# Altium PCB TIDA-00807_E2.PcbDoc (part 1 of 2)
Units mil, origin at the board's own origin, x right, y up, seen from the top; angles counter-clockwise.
Board outline 2559.06 x 2559.06 mil, 2 copper layers (Top Layer, Bottom Layer), stack 62 mil thick; 165 components, 78 nets, 356 pads, 106 vias.
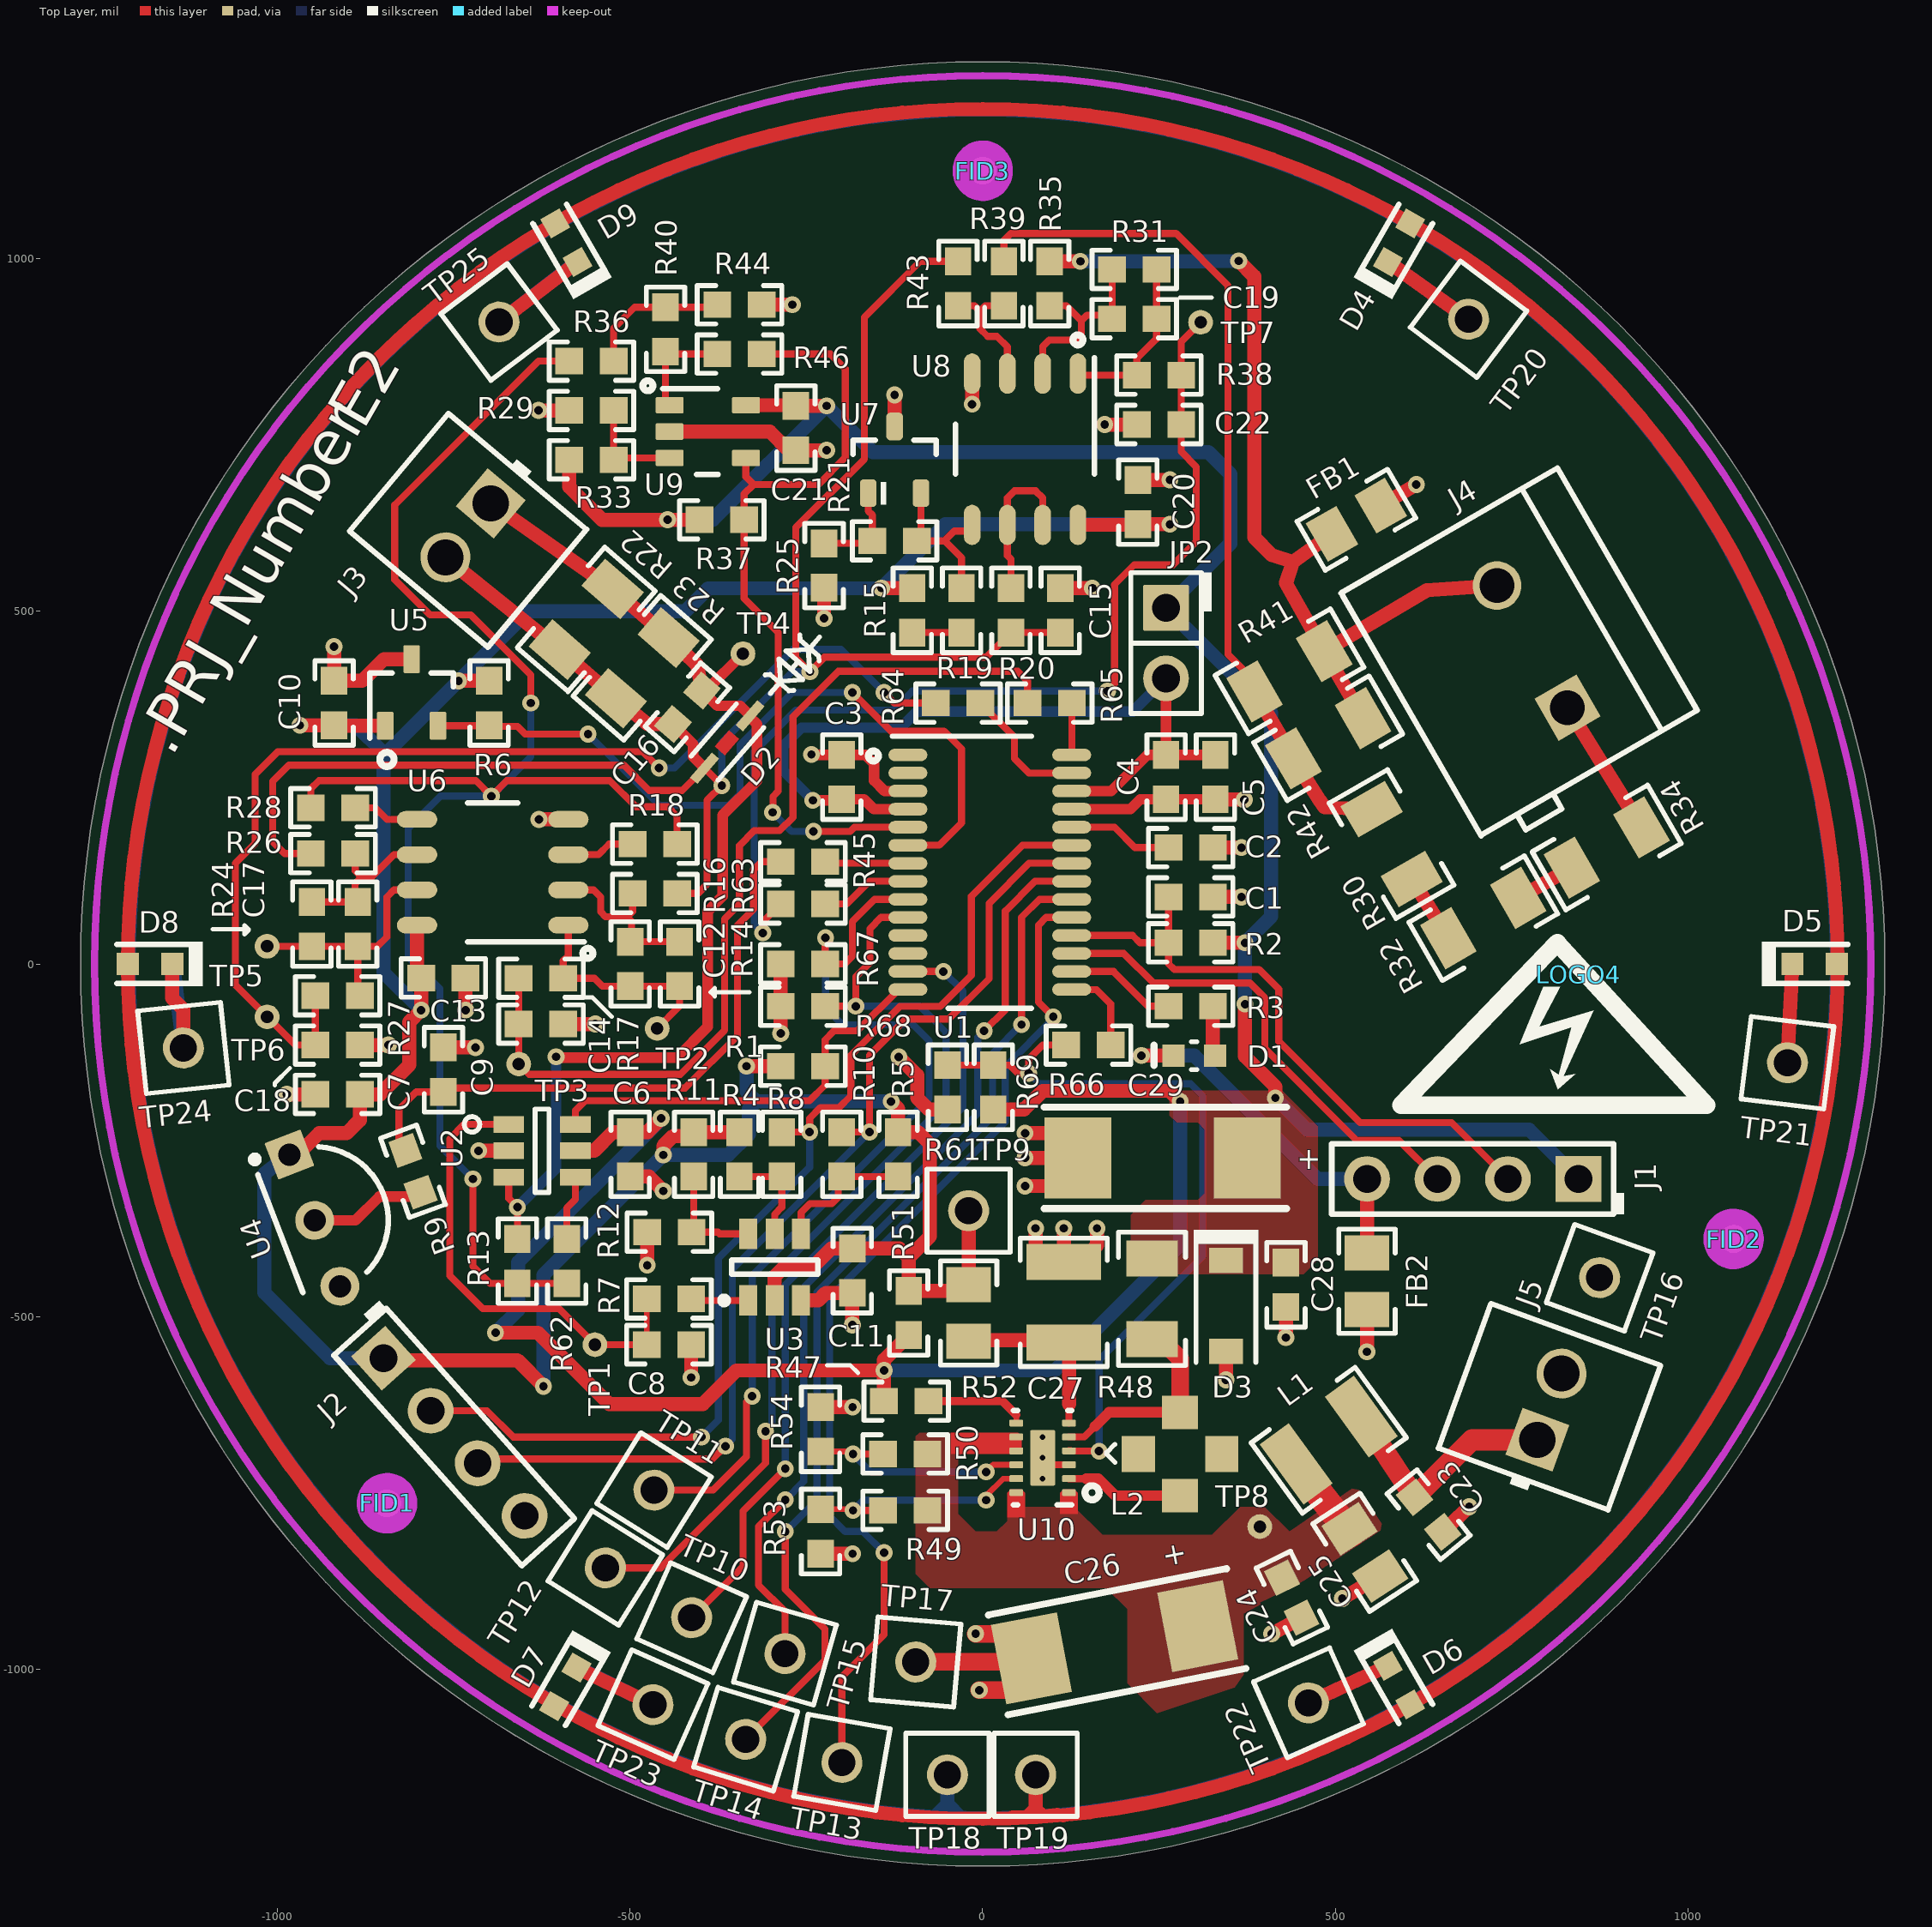
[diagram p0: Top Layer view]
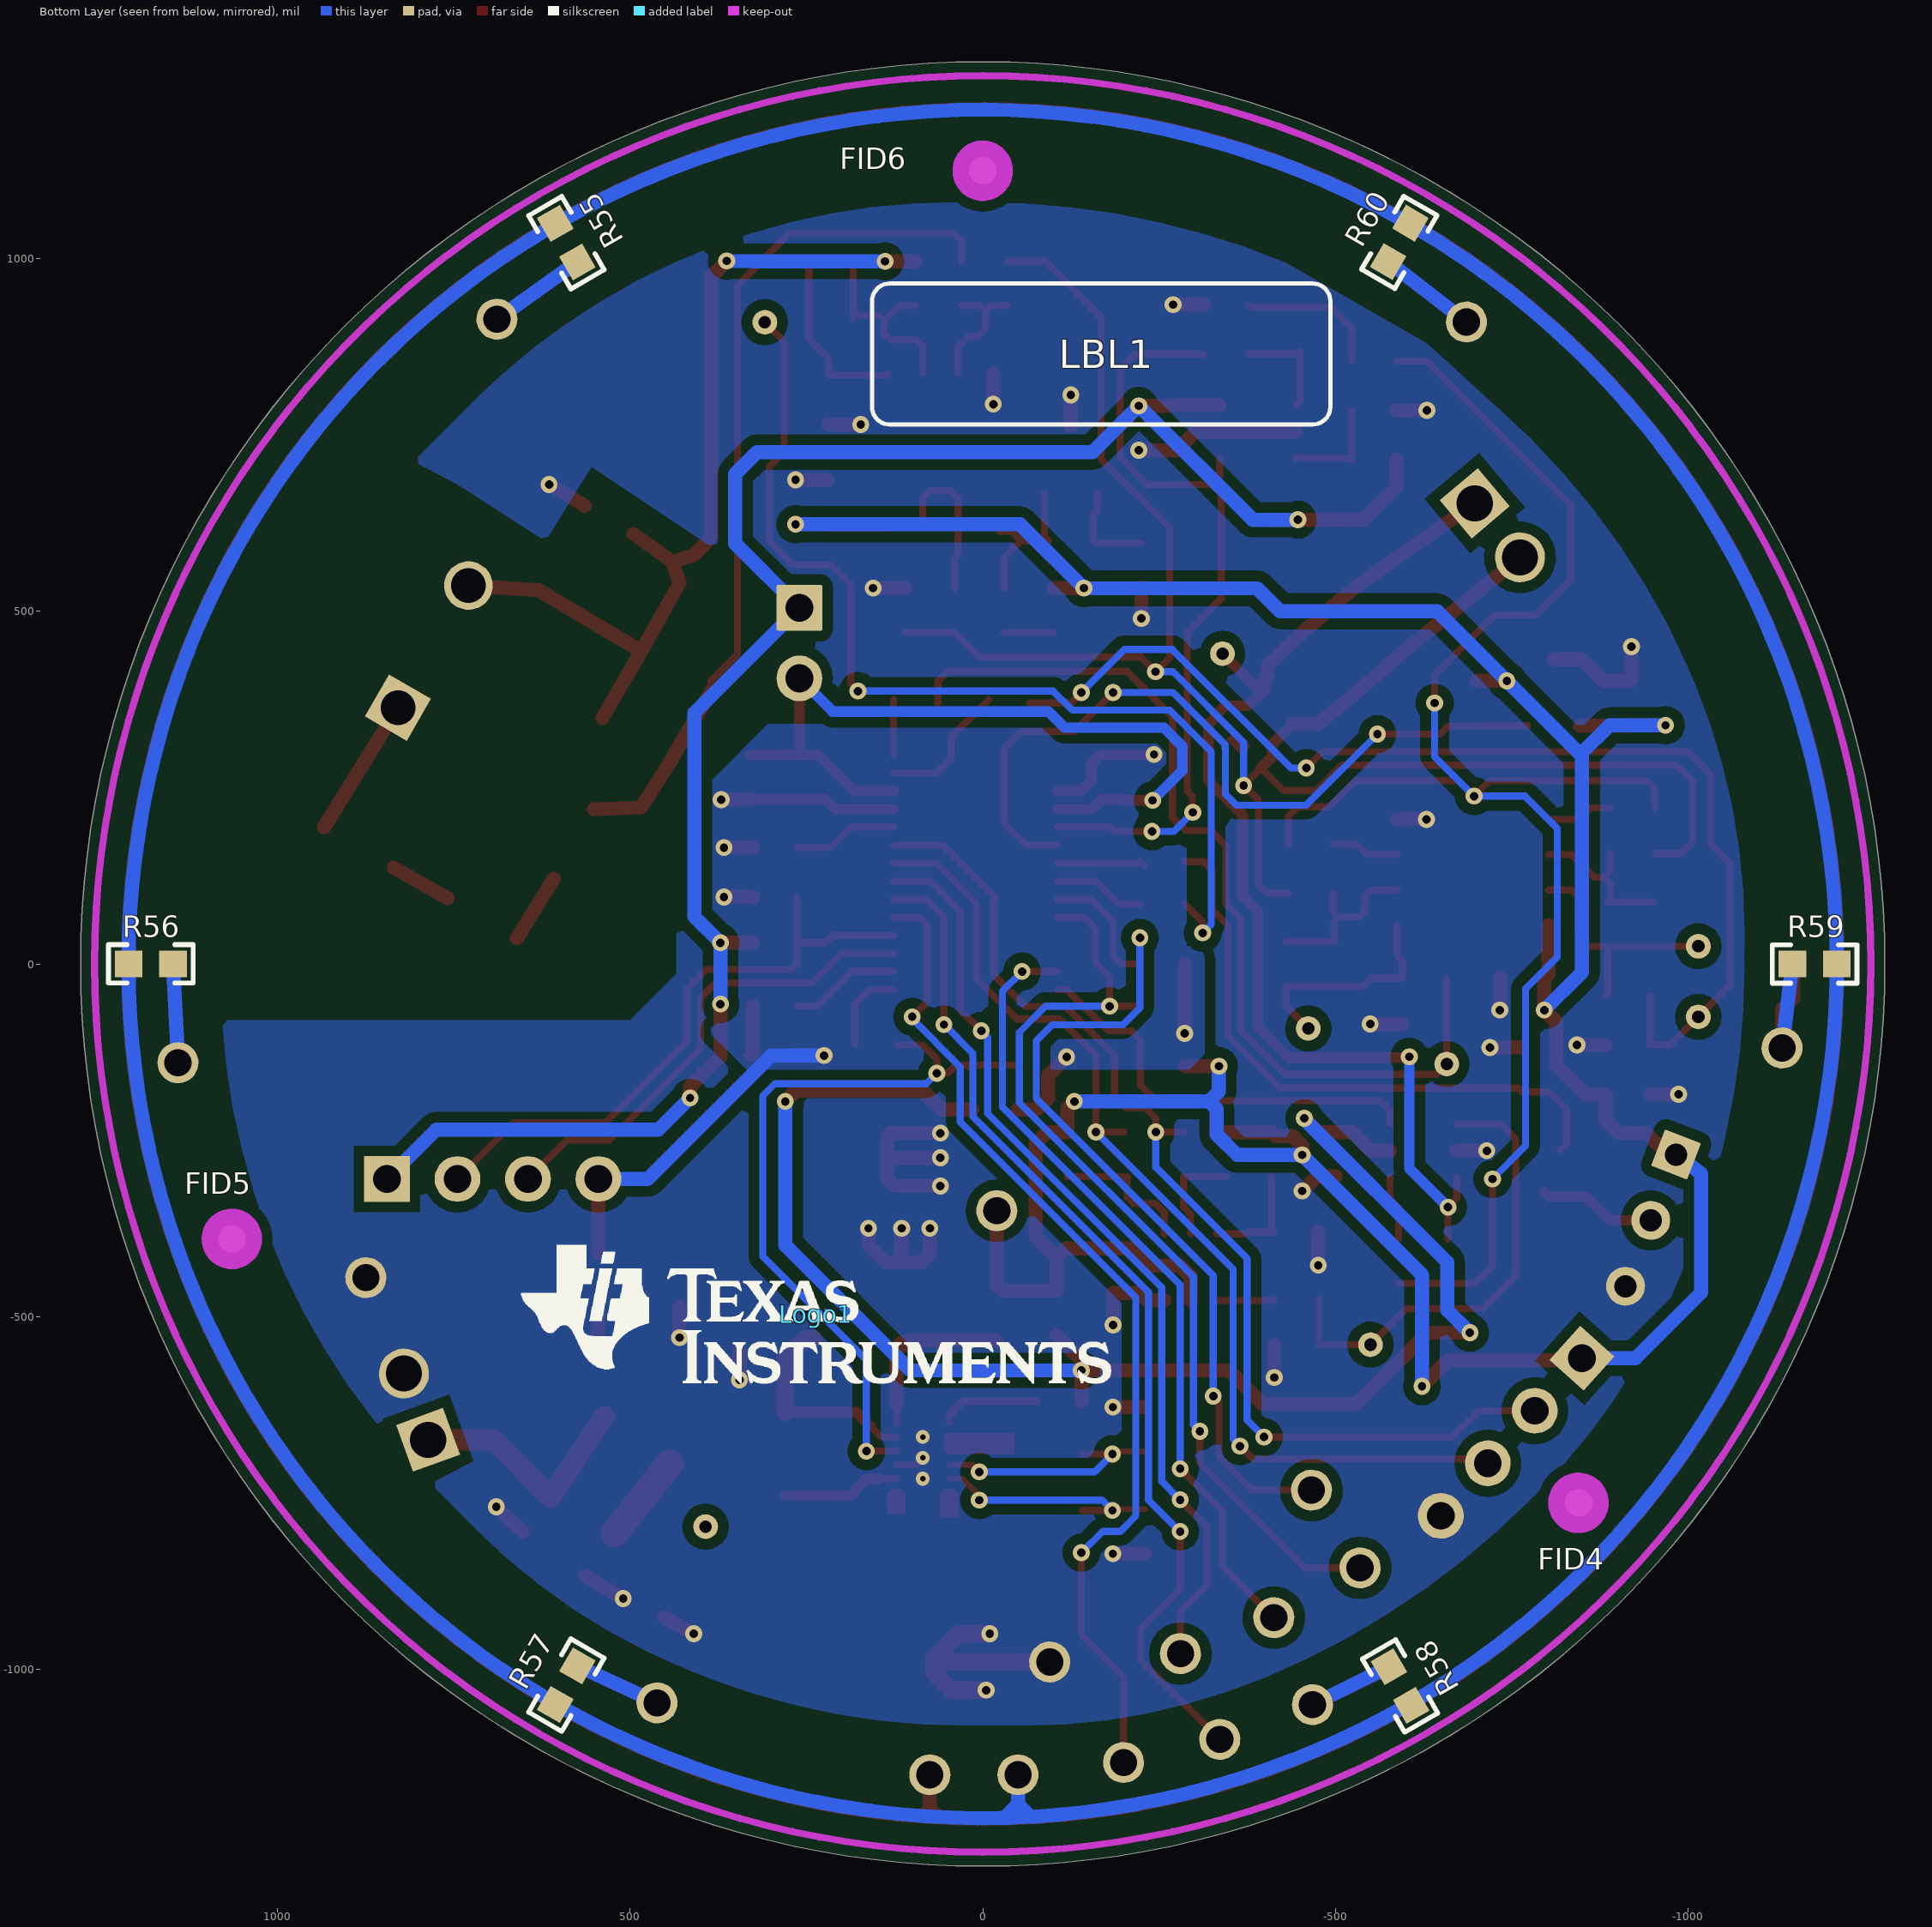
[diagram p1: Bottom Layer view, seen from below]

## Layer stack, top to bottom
Top Layer: signal copper 1.4
Dielectric: core 59.2, FR-4 High Tg, Dk 4.8
Bottom Layer: signal copper 1.4

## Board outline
0,-1279.53 cw(c0,0) -1279.53,0 cw(c0,0) 0,1279.53 cw(c0,0) 1279.53,0 cw(c0,0)

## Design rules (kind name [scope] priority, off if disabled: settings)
AcuteAngle [All] p1: minimum=4.50000000000000E+0001 checktracksonly=FALSE
AssemblyTestPointUsage [All] p1: valid=2
Clearance Clearance_Poly [InPolygon] p1: gap=15
Clearance [All] p2: gap=7.87
ComponentClearance ComponentClearance_MountingHoles_FiducialMarks [InComponentClass('Mounting Holes') vs InComponentClass('FiducialMark')] p1: gap=50 collisioncheckmode=3 verticalgap=10 showdistances=FALSE
ComponentClearance ComponentClearance_Shunt [InComponentClass('Header') vs InComponentClass('Shunt')] p2: gap=0 collisioncheckmode=3 verticalgap=0 showdistances=FALSE
ComponentClearance ComponentClearance_Logo [InComponentClass('Logo')] p3: gap=50 collisioncheckmode=3 verticalgap=10 showdistances=FALSE
ComponentClearance ComponentClearance_ScrewToNut [(HasFootprint('NY PMS 440 0025 PH')) vs (HasFootprint('Keystone_1902C'))] p4: gap=5 collisioncheckmode=3 verticalgap=10 showdistances=FALSE
ComponentClearance ComponentClearance_MountingHoles [InComponentClass('Mounting Holes')] p5: gap=250 collisioncheckmode=3 verticalgap=100000 showdistances=FALSE
ComponentClearance ComponentClearance_SmallPassives [HasFootprint('0201*') or HasFootprint('0402*') or HasFootprint('0508') or HasFootprint('0603*') or HasFootprint('0612') or HasFootprint('0805*') or HasFootprint('0815*') or HasFootprint('0830*') or HasFootprint('1206*') or HasFootprint('1210*') or HasFootprint('1808*') or HasFootprint('1812*') or HasFootprint('1825*') or HasFootprint('2010*') or HasFootprint('2220*') or HasFootprint('2225*') or HasFootprint('2512*') or HasFootprint('2728*') or HasFootprint('3518*') vs HasFootprint('0201*') or HasFootprint('0402*') or HasFootprint('0508') or HasFootprint('0603*') or HasFootprint('0612') or HasFootprint('0805*') or HasFootprint('0815*') or HasFootprint('0830*') or HasFootprint('1206*') or HasFootprint('1210*') or HasFootprint('1808*') or HasFootprint('1812*') or HasFootprint('1825*') or HasFootprint('2010*') or HasFootprint('2220*') or HasFootprint('2225*') or HasFootprint('2512*') or HasFootprint('2728*') or HasFootprint('3518*')] p6: gap=14.96 collisioncheckmode=3 verticalgap=10 showdistances=FALSE
ComponentClearance ComponentClearance_THtoSMT [IsThruComponent vs IsSMTComponent] p7: gap=40 collisioncheckmode=3 verticalgap=30 showdistances=FALSE
ComponentClearance ComponentClearance_THtoTH [IsThruComponent vs IsThruComponent] p8: gap=30 collisioncheckmode=3 verticalgap=30 showdistances=FALSE
ComponentClearance [All] p9: gap=30 collisioncheckmode=3 verticalgap=10 showdistances=FALSE
DiffPairsRouting [All] p1: maxlimit=100 minlimit=10 mostfreqgap=10 maxuncoupledlength=1000
FabricationTestPointUsage TestPointUsage [All] p1: valid=2 allowmultiple=FALSE
FabricationTestpoint Testpoint [All] p1: side=3 testpointundercomponent=TRUE minsize=40 maxsize=100 preferedsize=60 minholesize=0 maxholesize=40 preferedholesize=32 testpointgrid=1 allowsidetop=TRUE allowsidebottom=TRUE usegrid=TRUE gridtolerance=0.01
FanoutControl Fanout_LCC [IsLCC] p1: bgadir=Out bgaviamode=Centered fanoutstyle=Auto fanoutdirection=Alternating viagrid=1 // Fanout_LCC (Default Rule)
FanoutControl Fanout_BGA [IsBGA] p2: bgadir=Out bgaviamode=Centered fanoutstyle=Auto fanoutdirection=Alternating viagrid=1 // Fanout_BGA (Default Rule)
FanoutControl Fanout_Default [All] p4: bgadir=Out bgaviamode=Centered fanoutstyle=Auto fanoutdirection=Alternating viagrid=1 // Fanout_Default (Default Rule)
FanoutControl Fanout_Small [(CompPinCount < 5)] p5: bgadir=Out bgaviamode=Centered fanoutstyle=Auto fanoutdirection=OutThenIn viagrid=1 // Fanout_Small (Default Rule)
HoleSize [All] p1: absolutevalues=TRUE maxlimit=251 minlimit=7.87 maxpercent=80.000 minpercent=20.000
MinimumAnnularRing MinimumAnnularRing_ThermalPadVias [IsVia and InAnyComponent] p1: minimumring=5.91
MinimumAnnularRing [All] p2: minimumring=6
MinimumSolderMaskSliver MinimumSolderMaskSliver_Logo [InComponentClass('Logo') vs InComponentClass('Logo')] p1: minsoldermaskwidth=0.7
MinimumSolderMaskSliver [All] p2: minsoldermaskwidth=3.94
PlaneConnect [All] p1: planeconnectstyle=Relief reliefexpansion=10 reliefentries=4 reliefconductorwidth=10 reliefairgap=10
PolygonConnect PolygonConnect_Via [IsVia] p1: connectstyle=Direct reliefconductorwidth=10 reliefentries=4 polygonreliefangle="90 Angle"
PolygonConnect PolygonConnect_1 [All] p2: connectstyle=Direct reliefconductorwidth=15 reliefentries=4 polygonreliefangle="90 Angle"
RoutingVias ThermalPadVias [IsVia and InAnyComponent] p1: holewidth=7.87 width=19.68 viastyle="Through Hole" minholewidth=7.87 minwidth=19.68 maxholewidth=12.99 maxwidth=23.62
RoutingVias [All] p2: holewidth=12 width=24 viastyle="Through Hole" minholewidth=12 minwidth=24 maxholewidth=20 maxwidth=40
SilkToSilkClearance SilkToSilkClearance_Pb-FreeLogo [(HasFootprint('Pb-Free_Overlay_Medium') OR HasFootprint('Pb-Free_Overlay_Small')) vs (HasFootprint('Pb-Free_Overlay_Medium') OR HasFootprint('Pb-Free_Overlay_Small'))] p1: silktosilkclearance=0
SilkToSilkClearance [All] p2: silktosilkclearance=2
SilkscreenOverComponentPads SilkToComponentPadClearance [IsPad and InAnycomponent] p1 off: minsilkscreentomaskgap=5
SilkscreenOverComponentPads "Silk to Solder Mask Opening" [All] p2: minsilkscreentomaskgap=4
SolderMaskExpansion [All] p1: expansion=2.5
Width [All] p1: maxlimit=100 minlimit=6 preferedwidth=10 checkconnectedcopper=TRUE
14 further rules are at their usual default settings.

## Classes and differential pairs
component class "TIDA-00807_POWER SUPPLY": C23 C24 C25 C26 C27 C28 C29 D3 D4 D5 D6 D7 D8 D9 J5 L1 L2 R47 R48 R49 R50 R51 R52 R53 R54 R55 R56 R57 R58 R59 R60 TP8 TP9 TP16 TP17 TP18 TP19 TP20 TP21 TP22 TP23 TP24 TP25 U10
component class "TIDA-00807_OP_AMP and REFERENCE": C6 C7 C8 C9 C11 C12 C13 C14 C15 C16 C17 C18 C19 C20 C21 C22 D2 FB1 J3 J4 R4 R5 R7 R8 R9 R10 R11 R12 R13 R14 R15 R16 R17 R18 R19 R20 R21 R22 R23 R24 R25 R26 R27 R28 R29 R30 R31 R32 R33 R34 R35 R36 R37 R38 R39 R40 R41 R42 R43 R44 R46 R62 TP1 TP2 TP3 TP4 TP5 TP6 TP7 U2 U3 U4 U6 U7 U8 U9
component class TIDA-00807_MICROCONTROLLER: C1 C2 C3 C4 C5 C10 D1 FB2 J1 J2 JP2 R1 R2 R3 R6 R45 R61 R63 R64 R65 R66 R67 R68 R69 TP10 TP11 TP12 TP13 TP14 TP15 U1 U5
component class Label: LBL1
component class AssemblyNote: ZZ1 ZZ2 ZZ3 ZZ4
component class FiducialMark: FID1 FID2 FID3 FID4 FID5 FID6
component class TIDA-00807_EVM_Hardware: FID1 FID2 FID3 FID4 FID5 FID6 LBL1 Logo1 LOGO4 ZZ1 ZZ2 ZZ3 ZZ4
component class Logo: Logo1
component class Header: J1 J2 JP2

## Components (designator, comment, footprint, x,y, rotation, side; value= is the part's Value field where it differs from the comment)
C1 "GRM188R71C222KA01D" 0603#1 295,95 r0 top
C2 "C0603C474K9RACTU" 0603#1 295,165 r0 top
C3 "" 0603#1 -200,265 r90 top
C4 "" 0603#1 260,265 r270 top
C5 "GRM188R60J475ME19D" 0603#1 330,265 r270 top
C6 "" 0603#1 -500,-270 r270 top
C7 "" 0603#1 -915,-185 r180 top
C8 "C1608C0G1E103J" 0603#1 -445,-540 r180 top
C9 "C1608C0G1E103J" 0603#1 -765,-150 r270 top
C10 "GRM188R71E153KA01D" 0603#2 -920,370 r135 top
C11 "" 0603#1 -185,-435 r270 top
C12 "06033C101KAT2A" 0603#1 -500,0 r270 top
C13 "" 0603#1 -765,-20 r0 top
C14 "C1608C0G1E103J" 0603#1 -626.61,-85.24 r180 top
C15 "06033C104JAT2A" 0603#1 110,501.5 r270 top
C16 "06033C101KAT2A" 0603#1 -418.86,364.11 r229 top
C17 "06033C101KAT2A" 0603#1 -886.5,56.5 r270 top
C18 "C1608C0G1E103J" 0603#1 -915,-115 r180 top
C19 "06033C101KAT2A" 0603#1 215,915 r0 top
C20 "06033C104JAT2A" 0603#1 220,655 r270 top
C21 "06033C104JAT2A" 0603#1 -265,760 r90 top
C22 "C1608C0G1E103J" 0603#1 250,765 r0 top
C23 "06033C104JAT2A" 0603#1 632.47,-781.03 r309 top
C24 "06033C104JAT2A" 0603#1 438.37,-898.79 r296 top
C25 "C2012X5R1H475K125AB" 0805_HV 541.92,-834.48 r303 top
C26 "T491D336M010AT" CAP_POSCAP_D 186.99,-961.99 r191 top
C27 "1210YD106KAT2A" 1210 115,-480 r90 top
C28 "C0603C105K4PACTU" 0603#1 430,-455 r270 top
C29 "T491D336M010AT" CAP_POSCAP_D 255,-275 r180 top
D1 "LG L29K-G2J1-24-Z" "LG L29K_GREEN" 300,-130 r180 top
D2 "PESD3V3L1BA" DIO_SOD323 -362.26,314.91 r229 top
D3 "MMSZ4685T1G" SOD-123 345,-485 r270 top
D4 "150060GS75000" WL-SMCW_GREEN 590.55,1022.86 r60 top
D5 "150060GS75000" WL-SMCW_GREEN 1180,0 r0 top
D6 "150060GS75000" WL-SMCW_GREEN 590.55,-1022.86 r300 top
D7 "150060GS75000" WL-SMCW_GREEN -592,-1025.37 r240 top
D8 "150060GS75000" WL-SMCW_GREEN -1181.1,0 r180 top
D9 "150060GS75000" WL-SMCW_GREEN -590.55,1022.86 r120 top
FB1 "FBMJ2125HS420-T" 0805_hv 530,630 r30 top
FB2 "FBMJ2125HS420-T" 0805_hv 545,-450 r270 top
FID1 "Fiducial" Fiducial10-20 -845,-765 r0 top
FID2 "Fiducial" Fiducial10-20 1065,-390 r0 top
FID3 "Fiducial" Fiducial10-20 0,1125 r0 top
FID4 "Fiducial" Fiducial10-20 -845,-764.39 r180 bottom
FID5 "Fiducial" Fiducial10-20 1065,-390 r180 bottom
FID6 "Fiducial" Fiducial10-20 0,1125 r180 bottom
J1 "5-146278-4" TE_5-146278-4 695,-305 r180 top
J2 "5-146278-4" TE_5-146278-4 -749.78,-670.94 r311.82 top
J3 "OSTVN02A150" On-Shore_OSTVN02A150 -730,615 r230 top
J4 "ED120/2DS" CONN_ED120-2DS 779.42,450 r30 top
J5 "OSTVN02A150" On-Shore_OSTVN02A150 803.77,-627.97 r70 top
JP2 "5-146280-2" TSW-102-07-G-S 260,455 r270 top
L1 "B82422H1332K" 1210 490.8,-675.53 r216 top
L2 "744030002" WE-TPC_3510 280,-695 r0 top
LBL1 "Size: 0.65\" x 0.20 \"" Label_650x200 -168,865 r180 bottom
Logo1 "Texas Instruments" TI_Stacked_Overlay_Small 236,-497 r180 bottom
LOGO4 "DANGER HIGH VOLTAGE" IEC_HighVoltage_medium 845,-15 r0 top
R1 "RC0603FR-0747KL" 0603#1 -255,-145 r180 top
R2 "RC0603FR-0747KL" 0603#1 295,30 r0 top
R3 "RC0603FR-07680RL" 0603#1 295,-60 r0 top
R4 "RC0603FR-074K7L" 0603#1 -345,-270 r90 top
R5 "RC0603FR-074K7L" 0603#1 -120,-270 r90 top
R6 "RC0603FR-0730KL" 0603#1 -700,370 r90 top
R7 "CRCW0603100RFKEA" 0603#1 -445,-475 r180 top
R8 "RC0603FR-07220RL" 0603#1 -285,-270 r270 top
R9 "CRCW0603100RFKEA" 0603#1 -808.14,-294.14 r110 top
R10 "RC0603FR-07220RL" 0603#1 -200,-270 r270 top
R11 "RC0603FR-074K7L" 0603#1 -410,-270 r270 top
R12 "RC0603FR-074K7L" 0603#1 -444.36,-380.51 r0 top
R13 "ERJ-3GEY0R00V" 0603#1 -660,-421.5 r270 top
R14 "CRCW060310K0FKEA" 0603#1 -430,0 r270 top
R15 "CRCW0603100RFKEA" 0603#1 -100,501.5 r270 top
R16 "CRCW060310K0FKEA" 0603#1 -465,100 r180 top
R17 "CRCW0603100RFKEA" 0603#1 -626.61,-20.24 r180 top
R18 "CRCW060310K0FKEA" 0603#1 -465,170 r180 top
R19 "RC0603FR-07470RL" 0603#1 -30,501.5 r270 top
R20 "CRCW0603100RFKEA" 0603#1 40,501.5 r270 top
R21 "RC0603FR-0730KL" 0603#1 -125,600 r0 top
R22 "RC1206FR-0722RL" 1206 -562.26,488.76 r49 top
R23 "RC1206FR-0722RL" 1206 -483.01,419.88 r49 top
R24 "RC0603FR-0727KL" 0603#1 -951.5,56.5 r270 top
R25 "CRCW060310K0FKEA" 0603#1 -225,565 r90 top
R26 "CRCW060310K0FKEA" 0603#1 -921.5,156.5 r0 top
R27 "CRCW0603100RFKEA" 0603#1 -915,-45 r180 top
R28 "CRCW060310K0FKEA" 0603#1 -921.5,221.5 r0 top
R29 "CRCW0603100KFKEA" 0603#1 -555,785 r0 top
R30 "ERJ-8ENF3323V" 1206 580,170 r300 top
R31 "CRCW0603100KFKEA" 0603#1 215,985 r180 top
R32 "ERJ-8ENF3323V" 1206 710,65 r210 top
R33 "RC0603FR-0747KL" 0603#1 -555,715 r180 top
R34 "ERJ-8ENF3323V" 1206 885,165 r210 top
R35 "RC0603FR-0747KL" 0603#1 95,965 r90 top
R36 "CRCW060310K0FKEA" 0603#1 -555,855 r180 top
R37 "RC0603FR-0747KL" 0603#1 -370,630 r180 top
R38 "CRCW0603100RFKEA" 0603#1 250,835 r0 top
R39 "RC0603FR-0747KL" 0603#1 30,965 r90 top
R40 "CRCW060310K0FKEA" 0603#1 -450,900 r270 top
R41 "CRCW12062K80FKEA" 1206 435,415 r30 top
R42 "CRCW12062K80FKEA" 1206 490,320 r30 top
R43 "CRCW0603100KFKEA" 0603#1 -35,965 r90 top
R44 "RC0603FR-0730KL" 0603#1 -345,935 r180 top
R45 "ERJ-3GEY0R00V" 0603#1 -255,145 r180 top
R46 "CRCW06031M00FKEA" 0603#1 -345,865 r0 top
R47 "CRCW0603100KFKEA" 0603#1 -108.5,-620 r180 top
R48 "RC1206FR-071R02L" 1206 240,-475 r90 top
R49 "ERJ-3GEY0R00V" 0603#1 -110,-775 r0 top
R50 "ERJ-3GEY0R00V" 0603#1 -110,-695 r0 top
R51 "ERJ-3GEY0R00V" 0603#1 -105,-495 r270 top
R52 "CRCW08050000Z0EA" 0805_HV -20,-495 r90 top
R53 "ERJ-3GEY0R00V" 0603#1 -230,-805 r90 top
R54 "ERJ-3GEY0R00V" 0603#1 -230,-660 r270 top
R55 "CRCW0603220RJNEA" 0603#1 590.55,1022.86 r240 bottom
R56 "CRCW0603220RJNEA" 0603#1 1180,0 r180 bottom
R57 "CRCW0603220RJNEA" 0603#1 590.55,-1022.86 r120 bottom
R58 "CRCW0603220RJNEA" 0603#1 -592,-1024 r60.09 bottom
R59 "CRCW0603220RJNEA" 0603#1 -1180,0 r0 bottom
R60 "CRCW0603220RJNEA" 0603#1 -590.8,1023.29 r300 bottom
R61 "CRCW0603100KFKEA" 0603#1 -50,-175 r270 top
R62 "ERJ-3GEY0R00V" 0603#1 -590,-421.5 r90 top
R63 "ERJ-3GEY0R00V" 0603#1 -255,85 r180 top
R64 "ERJ-3GEY0R00V" 0603#1 -35,370 r180 top
R65 "ERJ-3GEY0R00V" 0603#1 95,370 r180 top
R66 "ERJ-3GEY0R00V" 0603#1 150,-115 r180 top
R67 "RC0603FR-0747KL" 0603#1 -255,0 r0 top
R68 "RC0603FR-0747KL" 0603#1 -255,-60 r0 top
R69 "CRCW0603100KFKEA" 0603#1 15,-175 r270 top
TP1 "TESTPOINT" TP_H045P075 -550,-540 r169.42 top
TP2 "TESTPOINT" TP_H045P075 -461.66,-91.52 r270 top
TP3 "TESTPOINT" TP_H045P075 -658.1,-141.9 r270 top
TP4 "TESTPOINT" TP_H045P075 -340,440 r0 top
TP5 "TESTPOINT" TP_H045P075 -1015,25 r0 top
TP6 "TESTPOINT" TP_H045P075 -1015,-75 r0 top
TP7 "TESTPOINT" TP_H045P075 309,910 r0 top
TP8 "TESTPOINT" TP_H045P075 393,-798 r90 top
TP9 "TP105-01-09" CC_TP105-01-09#1 -20,-350 r90 top
TP10 "TP105-01-09" CC_TP105-01-09#1 -412.84,-927.25 r246 top
TP11 "TP105-01-09" CC_TP105-01-09#1 -466.33,-746.28 r238 top
TP12 "TP105-01-09" CC_TP105-01-09#2 -535.22,-856.53 r238 top
TP13 "TP105-01-09" CC_TP105-01-09#1 -199.7,-1132.53 r80 top
TP14 "TP105-01-09" CC_TP105-01-09#1 -336.23,-1099.75 r73 top
TP15 "TP105-01-09" CC_TP105-01-09#1 -280.46,-978.08 r74 top
TP16 "TP105-01-09" CC_TP105-01-09#1 875,-445 r70 top
TP17 "TP105-01-09" CC_TP105-01-09#1 -95,-990 r355 top
TP18 "TP105-01-09" CC_TP105-01-09#1 -50,-1150 r0 top
TP19 "TP105-01-09" CC_TP105-01-09#1 75,-1150 r0 top
TP20 "TP105-01-09" CC_TP105-01-09#1 689.08,914.44 r143 top
TP21 "TP105-01-09" CC_TP105-01-09#1 1141.43,-140.15 r83 top
TP22 "TP105-01-09" CC_TP105-01-09#1 462,-1048 r24 top
TP23 "TP105-01-09" CC_TP105-01-09#1 -467.75,-1050.58 r336 top
TP24 "TP105-01-09" CC_TP105-01-09#1 -1133.76,-119.16 r276 top
TP25 "TP105-01-09" CC_TP105-01-09#1 -686.07,910.44 r217 top
U1 "MSP430FR5728IPWR" PW0028A_N 10,130 r0 top
U2 "SN74LVC1G3157DBVR" SOT23-6 -625,-265 r0 top
U3 "DAC101C081CIMK" MK06A_N -295,-430 r90 top
U4 "LMT87LPM" LP0003A -947.58,-363.74 r201 top
U5 "DRV5032FBDBZR" DBZ0003A_N -810,385 r90 top
U6 "OPA2317IDR" D0008A_N -695,130 r180 top
U7 "LM4041BIDBZ" SOT-23 -125,715 r90 top
U8 "OPA2317IDR" D0008A_N 60,730 r270 top
U9 "LMV331IDBV" DBV0005A_N -390,755 r0 top
U10 "TPS62740DSSR" DSS0012A 85,-700.47 r180 top
ZZ1 "This Assembly Note is for PCB labels only" AssemblyNoteLabel -1768,1971 r0 top
ZZ2 "These assemblies are ESD sensitive, ESD precautions shall be observed." AssemblyNote -1768,1862.11 r0 top
ZZ3 "These assemblies must be clean and free from flux and all contaminants. Use of no clean flux is not acceptable." AssemblyNote -1768,1773.56 r0 top
ZZ4 "These assemblies must comply with workmanship standards IPC-A-610 Class 2, unless otherwise specified." AssemblyNote -1768,1685 r0 top

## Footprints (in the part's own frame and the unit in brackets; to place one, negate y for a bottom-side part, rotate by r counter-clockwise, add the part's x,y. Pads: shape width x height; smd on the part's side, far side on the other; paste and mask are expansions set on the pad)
0603#1 [mm] "0603 from SM-752 data"
  rect 1x0.95 smd: 1(-0.8,0) 2(0.8,0)
  silkscreen extent -1.52,-0.69 1.52,0.69, body extent -0.87,-0.47 0.87,0.47, height 1
0603#2 [mm] "0603 from SM-752 data"
  rect 0.95x1 smd rot 45: 1(-0.566,0.566) 2(0.566,-0.566)
  silkscreen extent -1.57,-1.57 1.57,1.57, body extent -0.95,-0.95 0.95,0.95, height 1
0805_HV [mil] "0805 with 30mil clearance between pads"
  rect 50x63 smd: 1(-40,0) 2(40,0)
  silkscreen extent -74,-40 74,40, body extent -43,-29 43,29, height 57
0805_hv [mil] "0805 with 30mil clearance between pads"
  rect 50x63 smd: 1(-40,0) 2(40,0)
  silkscreen extent -74,-40 74,40, body extent -43,-29 43,29, height 57
1206 [mm] "1206 from SM-752 data"
  rect 1.3x1.85 smd: 1(-1.45,0) 2(1.45,0)
  silkscreen extent -2.4,-1.21 2.4,1.21, body extent -1.7,-0.9 1.7,0.9, height 1.35
1210 [mm] "1210 from SM-752 data"
  rect 1.3x2.7 smd: 1(-1.45,0) 2(1.45,0)
  silkscreen extent -2.32,-1.57 2.32,1.57, body extent -1.7,-1.35 1.7,1.35, height 1.35
AssemblyNote [mil] "Assembly Note"
AssemblyNoteLabel [mil] "Assembly Note for PCB Labels"
CAP_POSCAP_D [mil]
  rect 95x115 smd: 1(-120,0) 2(120,0)
  silkscreen extent -176,-72 168,72
CC_TP105-01-09#1 [mil] "Test-Point, Dia 100mil, TH"
  round 58.19 hole 38.5 mask+2.5: 1(0,0)
  silkscreen extent -59,-59 59,59, body extent -50,-50 50,50, height 180
CC_TP105-01-09#2 [mil] "Test-Point, Dia 100mil, TH"
  round 58.19 hole 38.5: 1(0,0)
  silkscreen extent -59,-59 59,59, body extent -50,-50 50,50, height 180
CONN_ED120-2DS [mm] "ONSHORE"
  rect 1.75x1.75 hole 1.25: 1(0,-2.54)
  round 1.75 hole 1.25: 2(0,2.54)
  silkscreen extent -5,-5.6 4,5.12, body extent -5,-5.6 4.15,5.12, height 13.1
D0008A_N [mm] "SOIC, 8-Leads, Body 4.9x3.9mm, Pitch 1.27mm, IPC Medium Density"
  oval 1.45x0.6 smd: 1(-2.725,1.905) 2(-2.725,0.635) 3(-2.725,-0.635) 4(-2.725,-1.905) 5(2.725,-1.905) 6(2.725,-0.635) 7(2.725,0.635) 8(2.725,1.905)
  silkscreen extent -3.3,-2.5 0.9,2.5, body extent -3,-2.45 3,2.45, height 1.63
DBV0005A_N [mm] "SOT23, 5-Leads, Body 2.9x1.6mm, Pitch 0.95mm, Lead Span 2.8mm, IPC Medium Density"
  rrect17% 1x0.6 smd: 1(-1.375,0.95) 2(-1.375,0) 3(-1.375,-0.95) 4(1.375,-0.95) 5(1.375,0.95)
  silkscreen extent -1.63,-1.55 0.38,1.55, body extent -1.42,-1.46 1.42,1.46, height 1.09
DBZ0003A_N [mm] "SOT23, 3-Leads, Body 2.9x1.3mm, Pitch 0.95mm, Lead Span 2.4mm, IPC Medium Density"
  rrect17% 1x0.6 smd: 1(-1.2,0.95) 2(-1.2,-0.95) 3(1.2,0)
  silkscreen extent -1.65,-1.5 0.7,1.5, body extent -1.26,-1.46 1.26,1.46, height 0.98
DIO_SOD323 [mm] "TVS DIODE, SOD323, SMT"
  rect 1.2x0.35 smd: 1(-1.25,0) 2(1.25,0)
  Top Layer region: -0.356,0.25 -0.357,-0.227 0.417,-0.227 0.415,0.25
  silkscreen extent -5.03,-0.65 1.25,0.65, body extent -1.25,-0.63 1.25,0.63, height 1.1
DSS0012A [mm] "SON, 12-Leads, Body 2x3mm, Pitch 0.5mm, Thermal Pad 2x0.9mm, TI Recommended"
  rrect40% 0.5x0.25 smd: 1(-0.95,1.25) 2(-0.95,0.75) 3(-0.95,0.25) 4(-0.95,-0.25) 5(-0.95,-0.75) 6(-0.95,-1.25) 7(0.95,-1.25) 8(0.95,-0.75) 9(0.95,-0.25) 10(0.95,0.25) 11(0.95,0.75) 12(0.95,1.25)
  rrect11% 0.9x0.9 on Top Paste: 13(0,0.55) 13(0,-0.55)
  rrect11% 0.9x2 smd paste-0.45: 13(0,0)
  silkscreen extent -1.05,-1.7 1.05,1.7, body extent -1,-1.5 1,1.5, height 0.8
Fiducial10-20 [mm]
  round 1 smd mask+0.5: 1(0,0)
  Top Layer keep-out circle w1.178: c0,0 r0.5
IEC_HighVoltage_medium [mil]
  silkscreen extent -252,-186 182,45
Label_650x200 [mil] "Thermal Transfer Label"
  silkscreen extent -325,-100 325,100, body extent -326,-101 326,101, height 1
"LG L29K_GREEN" [mm] "OSRAM"
  rect 0.8x0.8 smd paste-0.4: 1(-0.75,0) 2(0.75,0)
  silkscreen extent -0.1,-0.5 1.45,0.5, body extent -0.9,-0.45 0.9,0.45, height 0.67
LP0003A [mm] "TO, Flat Index; 3 In-Line, Formed Axial Leads; Body Dia. 4.8mm; Leads 0.56 x 0.41 mm (max)"
  rrect7% 1.4x1.4 hole 0.8: 1(0,-2.54)
  round 1.4 hole 0.8: 2(0,0) 3(0,2.54)
  silkscreen extent -2.65,-2.95 1.35,2.41, body extent -2.35,-2.83 1.33,2.83, height 9.01
MK06A_N [mm] "SOT23, 6-Leads, Body 3.0x1.7mm, Pitch 0.95mm, Lead Span 2.9mm, IPC Medium Density"
  rect 1.1x0.65 smd: 1(-1.2,0.95) 2(-1.2,0) 3(-1.2,-0.95) 4(1.2,-0.95) 5(1.2,0) 6(1.2,0.95)
  silkscreen extent -1.32,-1.55 0.25,1.95, body extent -0.9,-1.55 0.9,1.55, height 1
On-Shore_OSTVN02A150 [mm] "Terminal Block, 2.54mm, 2-pole, Brass, TH"
  rect 1.8x1.8 hole 1.3: 1(-1.27,0)
  round 1.8 hole 1.3: 2(1.27,0)
  silkscreen extent -3.1,-3.25 2.77,3.25, body extent -2.77,-3.25 2.77,3.25, height 8.51
PW0028A_N [mm] "TSOP, 28-Leads, Body 9.7x4.4mm, Pitch 0.65mm, IPC Medium Density"
  oval 1.4x0.45 smd: 1(-2.95,4.225) 2(-2.95,3.575) 3(-2.95,2.925) 4(-2.95,2.275) 5(-2.95,1.625) 6(-2.95,0.975) 7(-2.95,0.325) 8(-2.95,-0.325) 9(-2.95,-0.975) 10(-2.95,-1.625) 11(-2.95,-2.275) 12(-2.95,-2.925) 13(-2.95,-3.575) 14(-2.95,-4.225) 15(2.95,-4.225) 16(2.95,-3.575) 17(2.95,-2.925) 18(2.95,-2.275) 19(2.95,-1.625) 20(2.95,-0.975) 21(2.95,-0.325) 22(2.95,0.325) 23(2.95,0.975) 24(2.95,1.625) 25(2.95,2.275) 26(2.95,2.925) 27(2.95,3.575) 28(2.95,4.225)
  silkscreen extent -3.5,-4.9 1.5,4.9, body extent -3.21,-4.85 3.21,4.85, height 1
SOD-123 [mm] "On Semi recommended land pattern"
  rect 0.915x1.22 smd: 1(-1.637,0) 2(1.637,0)
  silkscreen extent -2.74,-1.17 2.03,1.17, body extent -1.93,-0.9 1.93,0.9, height 1.35
SOT23-6 [mm] "IC DAC R-R LP 12BIT SOT23-6"
  rect 1.1x0.6 smd: 1(-1.2,0.95) 2(-1.2,0) 3(-1.2,-0.95) 4(1.2,-0.95) 5(1.2,0) 6(1.2,0.95)
  silkscreen extent -2.8,-1.5 0.25,1.5, body extent -0.8,-1.45 0.8,1.45, height 1.45
SOT-23 [mm] "SOT23, 3-Leads, Body 2.9x1.3mm, Pitch 0.95mm, Lead Span 2.5mm, IPC Medium Density"
  rrect50% 1x0.6 smd: 1(-1.2,0.95) 2(-1.2,-0.95) 3(1.2,0)
  silkscreen extent -1.62,-1.5 0.7,1.5, body extent -1.16,-1.45 1.21,1.45, height 1
TE_5-146278-4 [mm] "TE CONNECTIVITY"
  rect 1.65x1.65 hole 1: 1(-3.81,0)
  round 1.65 hole 1: 2(-1.27,0) 3(1.27,0) 4(3.81,0)
  silkscreen extent -5.46,-1.27 5.08,1.27, body extent -4.95,-1.17 4.95,1.17, height 8.13
TI_Stacked_Overlay_Small [mil]
  silkscreen extent -418,-98 418,98
TP_H045P075 [mil] "TP_H0.45P0.75"
  round 35 hole 17.72: 1(0,0)
TSW-102-07-G-S [mm] "Samtec 100mil, 1x2, 230 mil above insulator"
  rrect6% 1.65x1.65 hole 1.016: 1(-1.27,0)
  round 1.65 hole 1.016: 2(1.27,0)
  silkscreen extent -2.54,-1.27 2.54,1.65, body extent -2.54,-1.27 2.54,1.27, height 8.38
WE-TPC_3510 [mm] "WURTH"
  rect 1.2x1.3 smd: 1(-1.5,0) 3(1.5,0)
  rect 1.3x1.2 smd: 2(0,-1.5) 4(0,1.5)
  silkscreen extent -2.65,-0.3 -2.35,0.35, body extent -2.5,-1.85 1.85,1.85, height 1.06
WL-SMCW_GREEN [mm] "WURTH"
  rect 0.8x0.8 smd: 1(-0.8,0) 2(0.8,0)
  silkscreen extent -1.9,-0.8 1.2,0.8, body extent -0.85,-0.45 0.85,0.45, height 0.8

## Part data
C1: "CAP, CERM, 2200 pF, 16 V, +/- 10%, X7R, 0603"
C2: "CAP, CERM, 0.47 µF, 6.3 V, +/- 10%, X7R, 0603"
C3 C4 C6 C7 C11 C13: library part 06033C104JAT2A, "CAP, CERM, 0.1uF, 25V, +/-5%, X7R, 0603"
C5: "CAP, CERM, 4.7 µF, 6.3 V, +/- 20%, X5R, 0603"
C8 C9 C14 C18 C22: "CAP, CERM, 0.01uF, 25V, +/-5%, C0G/NP0, 0603"
C10: "CAP, CERM, 0.015 µF, 25 V, +/- 10%, X7R, 0603"
C12 C16 C17 C19: "CAP, CERM, 100pF, 25V, +/-10%, X7R, 0603"
C15 C20 C21 C23 C24: "CAP, CERM, 0.1uF, 25V, +/-5%, X7R, 0603"
C25: "4.7µF ±10% 50V X5R Ceramic Capacitor"
C26 C29: library part CAP_TANT_47U_10V, "CAP TANT 33UF 10V 20% 2917"
C27: "CAP, CERM, 10uF, 16V, +/-10%, X5R, 1210"
C28: "CAP, CERM, 1uF, 16V, +/-10%, X5R, 0603"
D1 D4 D5 D6 D7 D8 D9: "LED, Green, SMD"
D2: "DIODE, TVS, BIDIRECTIONAL, 3.3VWM, 26VC, SOD323"
D3: "Diode, Zener, 3.6 V, 500 mW, SOD-123"
FB1 FB2: "FERRITE BEAD, 42 OHM, 4 A, DCR0.008 OHM, SMT-0805"
FID1 FID2 FID3 FID4 FID5 FID6: "Fiducial mark.  There is nothing to buy or mount."
J1 J2: "Header, 100mil, 4x1, Tin, TH"
J3 J5: "Terminal Block, 2.54mm, 2x1, Brass, TH"
J4: "TERMINAL BLOCK 5.08MM VERT 2POS, TH"
JP2: library part TSW-102-07-G-S, "Header, 100mil, 2x1, Gold, TH"
L1: library part IND_B82422H1332K, "Inductor, Chip, 3.3uH 770MA 1210 10%"
L2: "Inductor, Shielded Drum Core, Metal Composite, 2.2 µH, 0.74 A, 0.14 ohm, SMD"
LBL1: library part THT-14-423-10, "Thermal Transfer Printable Labels, 0.650\" W x 0.200\" H - 10,000 per roll"
Logo1: library part TI_Logo, "Texas Instrument Corporate Signature"
LOGO4: library part IEC_HighVoltage, "IEC 61010-1 High Voltage Warning"
R1 R2 R33 R35 R37 R39 R67 R68: "RES, 47.0 k, 1%, 0.1 W, 0603"
R3: "RES, 680, 1%, 0.1 W, 0603"
R4 R5 R11 R12: "RES, 4.70 k, 1%, 0.1 W, 0603"
R6 R44: "RES, 30.0 k, 1%, 0.1 W, 0603"
R7 R9 R15 R17 R20 R27 R38: "RES, 100 ohm, 1%, 0.1W, 0603"
R8 R10: "RES, 220, 1%, 0.1 W, 0603"
R13 R45 R49 R50 R51 R53 R54 R62 R63 R64 R65 R66: "RES, 0, 5%, 0.1 W, 0603"
R14 R16 R18 R25 R26 R28 R36: "RES, 10.0k ohm, 1%, 0.1W, 0603"
R19: "RES, 470 ohm, 1%, 0.1W, 0603"
R21: "RES, 30.0k ohm, 1%, 0.1W, 0603"
R22 R23: "RES, 22.0 ohm, 1%, 0.25W, 1206"
R24: "RES, 27.0k ohm, 1%, 0.1W, 0603"
R29 R31 R43 R47 R61 R69: "RES, 100k ohm, 1%, 0.1W, 0603"
R30 R32 R34: "RES, 332k ohm, 1%, 0.25W, 1206"
R40: library part RNCF0603TKY10K0, "RES, 10.0k ohm, 1%, 0.1W, 0603"
R41 R42: "RES, 2.80k ohm, 1%, 0.25W, 1206"
R46: "RES, 1.00Meg ohm, 1%, 0.1W, 0603"
R48: "RES, 1.02 ohm, 1%, 0.25W, 1206"
R52: "RES, 0 ohm, 5%, 0.125W, 0805"
R55 R56 R57 R58 R59 R60: "RES, 220 ohm, 5%, 0.1W, 0603"
TP1 TP2 TP3 TP4 TP5 TP6 TP7 TP8: library part TP_H0.45P0.75, "Testpoint"
TP9 TP10 TP11 TP12 TP13 TP14 TP15 TP16 TP17 TP18 TP19 TP20 TP21 TP22 TP23 TP24 TP25: "Test Point, Miniature, White, TH"
U1: "MIXED SIGNAL MICROCONTROLLER, PW0028A"
U2: "IC, SWITCH, SPDT, SOT23-6"
U3: "10-Bit Micro Power Digital-to-Analog Converter with an I2C-Compatible Interface, 6-pin Tiny SOT23"
U4: "Analog Temperature Sensors with Class-AB Output, LP0003A"
U5: "Ultra-Low Power Digital-Switch Hall Effect Sensor, DBZ0003A"
U6 U8: "Low-Offset, Rail-to-Rail I/O Operational Amplifier Precision Catalog, D0008A"
U7: "IC, Micropower Shunt Voltage Reference 100 ppm/°C, 45µA-12mA,  Adjustable"
U9: "Single General Purpose Low-Voltage Comparator, DBV0005A"
U10: "360nA IQ Step Down Converter for Low Power Applications, DSS0012A"
ZZ1: library part AssemblyNoteLabel
ZZ2 ZZ3 ZZ4: library part AssemblyNote

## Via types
v1: diameter 24, hole 12, Top Layer to Bottom Layer, tented both sides, 103 vias
v2: diameter 19.68, hole 7.87, Top Layer to Bottom Layer, 3 vias

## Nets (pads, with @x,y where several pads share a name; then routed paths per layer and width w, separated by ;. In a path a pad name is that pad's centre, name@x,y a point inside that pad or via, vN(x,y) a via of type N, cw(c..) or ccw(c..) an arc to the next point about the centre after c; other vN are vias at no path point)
3V3_A: C7.1 C10.1 C11.1 C13.1 C20.2 J2.1 R1.2 R4.2 R5.2 R6.2 R11.1 R15.1 R51.1 R52.2 TP9.1 U3.2 U4.1 U5.1 U6.8 U8.8 | length 4996
  Top Layer w20: U4.1@-983.42,-270.39 -971.39,-270.39 -941,-240 -902,-240 -883.5,-221.5 C7.1@-883.5,-185 -855,-185 -813.13,-143.13 -813.13,-82.13 v1(-796.5,-65.5) C13.1@-796.5,-20 -802.28,-14.21 U6.8@-802.28,55 ; v1(-968.5,338.5) C10.1@-920,338.5 -919.25,337.76 U5.1@-847.4,337.76 ; J2.1@-849.8,-559.17 -846.97,-562 -660,-562 v1(-623,-599) ; v1(-743.5,401.5) R6.2@-700,401.5 ; v1(-453,-271) -453,-258 -439,-244 -415.5,-244 R11.1@-410,-238.5 R4.2@-345,-238.5 ; v1(-335,-145) R1.2@-286.5,-145 ; U3.2@-295,-477.24 -295,-443 -280,-428 -239.2,-428 -214.7,-403.5 C11.1@-185,-403.5 -118.23,-403.5 -105,-416.74 ; v1(-143.5,532.99) R15.1@-100,532.99 ; v1(-130,-195) -120,-205 R5.2@-120,-238.5 -91.5,-238.5 -75,-255 -75,-386.74 -105,-416.74 ; TP9.1@-20,-350 R52.2@-20,-455 -28.5,-463.5 R51.1@-105,-463.5 -105,-416.74 ; U8.8@135,622.72 219.21,622.72 C20.2@220,623.5 v1(265.5,623.5)
  Bottom Layer w20: U4.1@-983.42,-270.39 -1018.97,-297.45 -1018.97,-466.03 -925.83,-559.17 J2.1@-849.8,-559.17 ; v1(-968.5,338.5) -889,338.5 -850,299.5 -850,294.99 ; v1(-796.5,-65.5) -850,-12 -850,294.99 ; v1(-623,-599) -623,-441 v1(-453,-271) -361,-271 -332,-242 -332,-206 -321,-195 ; v1(-335,-145) -335,-181 -321,-195 ; v1(-130,-195) -321,-195 ; v1(265.5,623.5) -52.98,623.5 v1(-143.5,532.99) -389.27,532.73 -422,500 -645,500 v1(-743.5,401.5) -850,294.99
3V3_PE: C27.1 R52.1 U10.6 | length 252
  Top Layer w10: U10.6@122.4,-651.26 122.4,-624.4
  Top Layer w20: R52.1@-20,-535 -18.5,-533.5 103.26,-533.5 C27.1@110.93,-541.16 ; C27.1@115,-537.09 122.4,-544.49 122.4,-624.4
CT_IP: C16.1 D2.1 J3.1 R13.1 R22.2 R23.2 TP4.1 U2.3 | length 1608.9
  Top Layer w10: U2.3@-672.24,-302.4 -672.24,-332.76 v1(-660,-345) R13.1@-660,-390
  Top Layer w15: v1(-605,-131.71) -603.83,-132.87 -433.87,-132.87 -390,-89.01 -390,75 -369,96 -369,211 -320,260 -320,340 -329.97,349.97 D2.1@-329.97,352.05 -343.92,366 -376.32,366 C16.1@-398.2,387.88 -392.12,387.88 TP4.1@-340,440
  Top Layer w20: J3.1@-697.86,653.3 R22.2@-524.81,531.85 R23.2@-445.56,462.96 -405,424 C16.1@-398.2,387.88
  Bottom Layer w15: v1(-660,-345) -605,-290 v1(-605,-131.71)
CUR_H: C18.2 R27.2 R64.2 TP6.1 | length 1618.6
  Top Layer w10: R27.2@-946.5,-45 C18.2@-946.5,-115 -975,-115 TP6.1@-1015,-75 -1060,-30 -1060,143 -1032,171 -1032,269 -1000,301 -482,301 v1(-459,278) ; v1(-140,385) -125,370 R64.2@-66.5,370
  Bottom Layer w10: v1(-459,278) -437,278 -269.05,445.95 -200.95,445.95 v1(-140,385)
CUR_IP: R13.2 R18.1 R28.1 R36.2 R62.1 | length 2453.4
  Top Layer w10: R28.1@-952.99,221.5 -952.99,248.5 -941.5,260 -719,260 v1(-697,238) -675,260 -529,260 -492,223 -447,223 -433.5,209.5 R18.1@-433.5,170 ; v1@-718,-305 -723,-310 -723,-429 -699.01,-452.99 R13.2@-660,-452.99 R62.1@-590,-452.99 ; v1(-641,370) -641,410 -726,495 -784,495 -834,545 -834,651 -630,855 R36.2@-586.5,855
  Bottom Layer w10: v1(-723,-305) -770,-258 -770,-35 -815,10 -815,192.28 -769.28,238 v1(-697,238) -641,294 v1(-641,370)
CUR_L: C14.2 R17.2 R65.2 TP3.1 | length 1348.1
  Top Layer w10: R17.2@-658.1,-20.24 C14.2@-658.1,-85.24 TP3.1@-658.1,-141.9 -643.42,-156.58 -428.58,-156.58 -366,-94 -366,64 -345,85 -345,168 -324,189 -288,189 -269,208 -269,351 -205,415 50,415 63.5,401.5 R65.2@63.5,370
DGND: C6.2 C7.2 C8.1 C9.1 C10.2 C11.2 C13.2 C14.1 C15.1 C18.1 C20.1 C21.1 C22.1 C23.2 C24.2 C25.2 C26.2 C27.2 C28.2 C29.2 D3.2 FB1.2 FB2.2 J2.4 J5.2 R12.1 R25.1 R29.1 R44.1 R53.1 R54.1 TP16.1 TP17.1 U2.2 U3.3 U4.3 U5.3 U6.4 U7.3 U8.4 U9.2 U10.3 U10.13@85,-700.47 | length 2697.7
  Top Layer w10: v2(85,-700.47) 94.84,-710.31 U10.3@122.4,-710.31
  Top Layer w20: v1(-987,-185) C7.2@-946.5,-185 ; v1(-920,450) C10.2@-920,401.5 -880.12,401.5 -849.37,432.24 U5.3@-810,432.24 ; C18.1@-883.5,-115 v1(-843,-115) ; C9.1@-765,-118.5 v1(-719.5,-118.5) ; v1(-733.5,-65.5) C13.2@-733.5,-20 ; v1(-715,-265) U2.2@-672.24,-265 ; v1(-629.99,785) R29.1@-586.5,785 ; v1(-629.5,205) U6.4@-587.72,205 ; C14.1@-595.11,-85.24 v1(-549.61,-85.24) ; C6.2@-500,-301.5 -473.5,-301.5 v1(-453,-322) ; v1(-475.85,-427.31) R12.1@-475.85,-380.51 ; U9.2@-444.13,755 -302,755 -275.5,728.5 C21.1@-265,728.5 v1(-221.5,728.5) ; v1(-413.5,-586.53) C8.1@-413.5,-540 ; R44.1@-313.5,935 v1(-270.01,935) ; U3.3@-257.6,-477.24 -233.24,-477.24 -222.5,-466.5 C11.2@-185,-466.5 ; R53.1@-230,-836.5 v1(-184.5,-836.5) ; R54.1@-230,-628.5 v1(-184.5,-628.5) ; v1(-225,490.01) R25.1@-225,533.5 ; C11.2@-187.12,-468.61 C11.2@-185,-466.5 ; v1(-185,-512) C11.2@-185,-466.5 ; U7.3@-125,762.24 v1(-125,807) ; v1(-15,793.79) U8.4@-15,837.28 ; v1(60,-315) 125,-315 135,-305 C29.2@135,-275 ; v1(60,-275) C29.2@135,-275 ; v1(60,-240) 130,-240 135,-245 C29.2@135,-275 ; v1(75,-375) 75,-411 86.91,-422.91 C27.2@115,-422.91 ; C15.1@110,532.99 v1(155.5,532.99) ; v1(115,-375) C27.2@115,-422.91 ; v1(162,-375) 162,-399 138.09,-422.91 C27.2@115,-422.91 ; v1(173,765) C22.1@218.5,765 ; C20.1@220,686.5 v1(265.5,686.5) ; v1(345,-590) D3.2@345,-549.47 ; v1(410,-950) C24.2@452.18,-927.1 ; v1(430,-530) C28.2@430,-486.5 ; v1(510,-900) C25.2@563.7,-868.02 ; v1(545,-550) FB2.2@545,-490 ; FB1.2@564.64,650 v1(615,680) ; C23.2@652.29,-805.51 v1(690,-770)
  Top Layer w25: TP17.1@-95,-990 C26.2@69.2,-990 ; v1(-10,-950) 34.31,-950 C26.2@69.2,-984.89 C26.2@69.2,-990 ; v1(-5,-1030) 44.62,-1030 69.2,-1005.42 C26.2@69.2,-990
  other v2: 85,-730 85,-670.94
FAULT: R37.1 R46.2 U1.5 U9.4 | length 1140.6
  Top Layer w10: U9.4@-335.87,717.6 -335.87,690.87 -325,680 ; R46.2@-313.5,865 -216,865 -195,844 -195,718 -233,680 -325,680 ; v1(-298,215) -297.5,215.5 -297.5,237.5 -290,245 -290,469.82 -290.13,469.95 -290.13,470.13 -338.5,518.5 R37.1@-338.5,630 -338.5,666.5 -325,680 ; v1(-240,188) -188,188 -182.02,193.98 U1.5@-106.14,193.98
  Bottom Layer w10: v1(-298,215) -271,188 v1(-240,188)
GND: C1.2 C2.2 C3.2 C4.2 C5.2 D1.2 FB2.1 J1.4 R61.2 R67.1 R68.1 U1.3 U1.25 | length 1265.8
  Top Layer w15: v1(-243,297) -242.5,296.5 C3.2@-200,296.5 -166.5,296.5 -154,284 -154,260 -139.16,245.16 U1.3@-106.14,245.16 ; U1.25@126.14,219.57 209.57,219.57 223.5,233.5 C4.2@260,233.5 C5.2@330,233.5
  Top Layer w20: v1(-286.5,-98.5) R68.1@-286.5,-60 R67.1@-286.5,0 ; v1(-119,-132) -93,-158 -93,-190 -76.5,-206.5 R61.2@-50,-206.5 ; v1(224.97,-130) D1.2@270.47,-130 ; C1.2@326.5,93.5 C1.2@326.5,95 v1(366.99,95) ; C2.2@326.5,165 v1(366.99,165) ; C5.2@330,233.5 330.5,233 v1(371,233) ; FB2.1@545,-410 J1.4@545,-305
  Bottom Layer w20: v1(224.97,-130) 300,-130 475,-305 J1.4@545,-305
HALL_OUT: R6.1 U1.6 U5.2 | length 1122.4
  Top Layer w10: U5.2@-772.6,337.76 -700.75,337.76 R6.1@-700,338.5 ; R6.1@-698.5,337 -660,337 -649.07,326.07 v1(-559.8,326.07) ; v1(-185,385) -130,330 -55,330 -30,305 -30,200 -61.61,168.39 U1.6@-106.14,168.39
  Bottom Layer w10: v1(-559.8,326.07) -458.73,225 -360,225 -344.13,240.87 -344.13,306.33 -344,306.46 -344,311 -270,385 v1(-185,385)
I2C_SCL: J2.2 R8.1 U1.23 | length 1585.9
  Top Layer w10: J2.2@-783.12,-633.68 -703.32,-633.68 -666,-671 v1(-399,-671) ; R8.1@-285,-238.5 v1(-245.5,-238.5) -245.5,-219.25 -230.25,-204 -204,-204 -187,-187 -187,-129.46 -117.62,-60.08 -60.08,-60.08 -16,-16 -16,96 56.39,168.39 U1.23@126.14,168.39
  Bottom Layer w10: v1(-399,-671) -375,-647 -375,-418 -245.5,-288.5 v1(-245.5,-238.5)
I2C_SDA: J2.3 R10.1 U1.22 | length 1503.3
  Top Layer w10: J2.3@-716.43,-708.2 -710.23,-702 -383,-702 v1(-365,-684) ; R10.1@-200,-238.5 v1(-160.5,-238.5) -160.5,-129.5 -109.08,-78.08 -48.08,-78.08 9,-21 9,86 65.8,142.8 U1.22@126.14,142.8
  Bottom Layer w10: v1@-366,-684 v1(-365,-684) -355,-674 -355,-433.01 v1(-160.5,-238.5)
N1: FB1.1 J4.2 R35.2 R41.2 R42.2 | length 1325.5
  Top Layer w20: R35.2@95,996.5 v1(138.5,996.5) ; v1(363,997) 385,975 385,605 410,580 440,570 ; FB1.1@495.36,610 440,570 ; R42.2@539.44,348.54 R41.2@484.44,443.54 ; J4.2@729.42,536.6 630,530 R41.2@484.44,443.54 ; 440,570 430,540 R41.2@484.44,443.54
  Bottom Layer w20: v1(138.5,996.5) 326.5,996.5 v1(363,997)
NetC1_1: C1.1 J1.2 R2.1 U1.18 | length 887.7
  Top Layer w10: U1.18@126.14,40.43 212.57,40.43 223,30 R2.1@263.5,30 ; C1.1@263.5,95 R2.1@263.5,30 ; J1.2@745,-305 665,-225 535,-225 420,-110 420,-36 392,-8 271.8,-8 263.5,0.3 R2.1@263.5,30
NetC2_1: C2.1 U1.24 | length 149.4
  Top Layer w10: U1.24@126.14,193.98 187.02,193.98 216,165 C2.1@263.5,165
NetC3_1: C3.1 C4.1 C5.1 JP2.2 U1.4 U1.26 | length 1152
  Top Layer w15: v1(-241,232) -201.5,232 C3.1@-200,233.5 -168.5,233.5 -154.57,219.57 U1.4@-106.14,219.57 ; U1.26@126.14,245.16 182.16,245.16 233.5,296.5 C4.1@260,296.5 ; JP2.2@260,405 C4.1@260,296.5 ; C5.1@330,296.5 C4.1@260,296.5
  Bottom Layer w15: v1(-241,232) -283,274 -283,309 -257,335 -116,335 -93,358 213,358 JP2.2@260,405
NetC8_2: C8.2 R7.2 TP1.1 U2.1 | length 671.3
  Top Layer w8: C8.2@-476.5,-540 R7.2@-476.5,-475
  Top Layer w10: U2.1@-672.24,-227.6 -735.6,-227.6 -756,-248 -756,-442 -709,-489 -601,-489 TP1.1@-550,-540 C8.2@-476.5,-540
NetC12_1: C12.1 R14.1 R16.2 U6.2 | length 256.7
  Top Layer w10: U6.2@-587.72,105 -552,105 -542,95 -542,74 -535,67 -504,67 ; R16.2@-496.5,100 -496.5,74.5 -504,67 ; R14.1@-430,31.5 C12.1@-500,31.5 -498,33.5 -498,60 -504,66 -504,67
NetC12_2: C12.2 R14.2 R17.1 TP2.1 U6.1 | length 321.2
  Top Layer w10: U6.1@-587.72,55 -587.72,11.85 -595.11,4.46 R17.1@-595.11,-20.24 -550.76,-20.24 -539.5,-31.5 C12.2@-500,-31.5 R14.2@-430,-31.5 -430,-59.85 TP2.1@-461.66,-91.52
